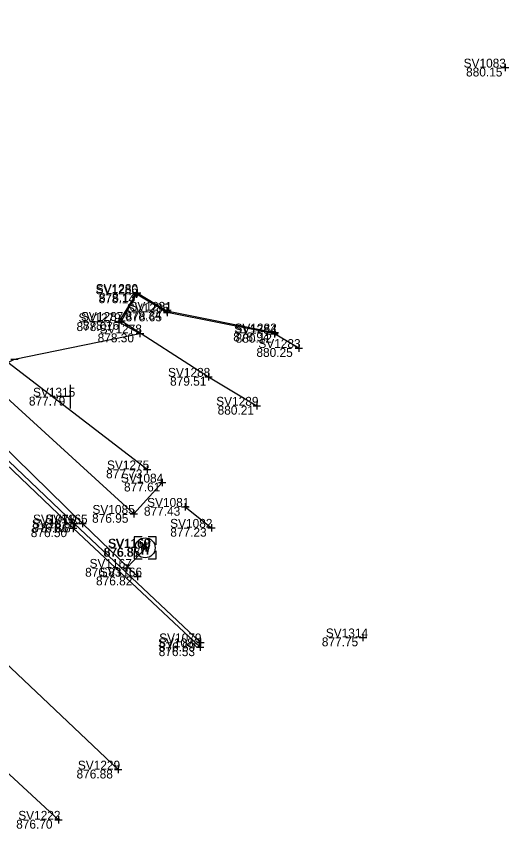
# Model space of a CAD drawing. Extents: x 1480001 to 1480402, y 379235 to 379603.
# Drawn here: x 1480335.4 to 1480401.9, y 379251.1 to 379360.8 of the extents above; entities that cross this region are included whole.
import ezdxf

# ---------------------------------------------------------------- set-up
doc = ezdxf.new("R2010")
doc.units = 0
for name, color, linetype in [('BD_X_Building', 7, 'Continuous'), ('PM_P_CL_Double_Solid', 7, 'Continuous'), ('PM_X_Lane_Line', 7, 'Continuous'), ('PV_X_Curb', 7, 'Continuous'), ('PV_X_Driveway', 7, 'Continuous'), ('PV_X_Walk', 7, 'Continuous'), ('SN_X_Public', 7, 'Continuous'), ('SV_X_Shot_Marker', 7, 'Continuous'), ('SV_X_Text_Elevation', 7, 'Continuous'), ('SV_X_Text_Name', 7, 'Continuous'), ('UT_X_Water', 7, 'Continuous'), ('UT_X_Water_Cells', 7, 'Continuous')]:
    doc.layers.add(name, color=color, linetype=linetype)

msp = doc.modelspace()

# ---------------------------------------------------------------- linework, layer by layer
at = {"layer": 'BD_X_Building'}
msp.add_line((1480358.23, 379294.55), (1480361.77, 379291.72), dxfattribs=at)
at = {"layer": 'PM_P_CL_Double_Solid'}
msp.add_lwpolyline([(1480349.17, 379259.05), (1480326.95, 379280.06), (1480305.57, 379299.92), (1480284.39, 379319.58), (1480263.3, 379339.27), (1480242.58, 379359.21), (1480224.61, 379376.17), (1480208.19, 379391.53)], dxfattribs=at)
at = {"layer": 'PM_X_Lane_Line'}
msp.add_line((1480333.91, 379258.95), (1480341.1, 379252.27), dxfattribs=at)
at = {"layer": 'PV_X_Curb'}
for points in [[(1480221.5, 379406.23), (1480232.96, 379395.54), (1480249.63, 379380.04), (1480261.65, 379368.64), (1480263.97, 379366.42), (1480266.34, 379364.24), (1480284.17, 379347.24), (1480298.68, 379333.41), (1480300.4, 379332.23), (1480315.33, 379318.04), (1480323.87, 379309.98), (1480343.09, 379291.66), (1480360.25, 379275.58)], [(1480221.91, 379406.57), (1480233.16, 379396.15), (1480249.93, 379380.31), (1480262.01, 379368.89), (1480262.35, 379369.25), (1480264.51, 379367.17), (1480266.63, 379365.06), (1480266.41, 379364.74), (1480284.49, 379347.54), (1480298.92, 379333.84), (1480300.74, 379332.59), (1480315.86, 379318.31), (1480323.78, 379310.75), (1480324.55, 379310.08), (1480343.24, 379292.3), (1480360.29, 379276.24)]]:
    msp.add_lwpolyline(points, dxfattribs=at)
at = {"layer": 'PV_X_Driveway'}
msp.add_lwpolyline([(1480353.09, 379299.61), (1480334.27, 379314.05), (1480335.15, 379314.52), (1480352.11, 379317.98), (1480349.25, 379319.5), (1480351.71, 379323.45), (1480355.72, 379321.04), (1480370.32, 379318.11)], dxfattribs=at)
at = {"layer": 'PV_X_Walk'}
for points in [[(1480355.12, 379297.83), (1480351.29, 379293.6), (1480334.1, 379309.33), (1480328.21, 379315.43), (1480328.74, 379316.33), (1480319.91, 379324.49), (1480307.61, 379335.13), (1480302.9, 379338.36), (1480281.82, 379358.41), (1480285.61, 379363.39), (1480280.44, 379367.11), (1480277.22, 379362.83), (1480260.82, 379378.02), (1480244.57, 379393.15), (1480235.61, 379401.34), (1480215.34, 379421.05)], [(1480373.55, 379316.01), (1480370.27, 379317.93), (1480355.8, 379320.82), (1480351.65, 379323.27), (1480349.6, 379319.67), (1480361.36, 379312.12), (1480367.87, 379308.21)]]:
    msp.add_lwpolyline(points, dxfattribs=at)
at = {"layer": 'SN_X_Public'}
for p, q in [((1480342.69, 379311.04), (1480342.69, 379307.84)), ((1480342.69, 379309.44), (1480341.09, 379309.44))]:
    msp.add_line(p, q, dxfattribs=at)
at = {"layer": 'SV_X_Shot_Marker'}
for p, q in [((1480401.4, 379354.4), (1480401.4, 379353.4)), ((1480400.9, 379353.9), (1480401.9, 379353.9)), ((1480401.4, 379353.9), (1480401.4, 379353.9)), ((1480351.15, 379323.27), (1480352.15, 379323.27)), ((1480351.21, 379323.45), (1480352.21, 379323.45)), ((1480351.65, 379323.77), (1480351.65, 379322.77)), ((1480351.65, 379323.27), (1480351.65, 379323.27)), ((1480351.71, 379323.95), (1480351.71, 379322.95)), ((1480351.71, 379323.45), (1480351.71, 379323.45)), ((1480355.22, 379321.04), (1480356.22, 379321.04)), ((1480355.72, 379321.54), (1480355.72, 379320.54)), ((1480355.72, 379321.04), (1480355.72, 379321.04)), ((1480355.8, 379321.32), (1480355.8, 379320.32)), ((1480349.25, 379320), (1480349.25, 379319)), ((1480349.6, 379320.17), (1480349.6, 379319.17)), ((1480355.3, 379320.82), (1480356.3, 379320.82)), ((1480355.8, 379320.82), (1480355.8, 379320.82)), ((1480348.75, 379319.5), (1480349.75, 379319.5)), ((1480349.1, 379319.67), (1480350.1, 379319.67)), ((1480349.25, 379319.5), (1480349.25, 379319.5)), ((1480349.6, 379319.67), (1480349.6, 379319.67)), ((1480351.61, 379317.98), (1480352.61, 379317.98)), ((1480352.11, 379318.48), (1480352.11, 379317.48)), ((1480352.11, 379317.98), (1480352.11, 379317.98)), ((1480369.77, 379317.93), (1480370.77, 379317.93)), ((1480369.82, 379318.11), (1480370.82, 379318.11)), ((1480370.27, 379318.43), (1480370.27, 379317.43)), ((1480370.27, 379317.93), (1480370.27, 379317.93)), ((1480370.32, 379318.61), (1480370.32, 379317.61)), ((1480370.32, 379318.11), (1480370.32, 379318.11)), ((1480373.05, 379316.01), (1480374.05, 379316.01)), ((1480373.55, 379316.51), (1480373.55, 379315.51)), ((1480373.55, 379316.01), (1480373.55, 379316.01)), ((1480334.65, 379314.52), (1480335.65, 379314.52)), ((1480361.36, 379312.62), (1480361.36, 379311.62)), ((1480360.86, 379312.12), (1480361.86, 379312.12)), ((1480361.36, 379312.12), (1480361.36, 379312.12)), ((1480367.37, 379308.21), (1480368.37, 379308.21)), ((1480367.87, 379308.71), (1480367.87, 379307.71)), ((1480367.87, 379308.21), (1480367.87, 379308.21)), ((1480352.59, 379299.61), (1480353.59, 379299.61)), ((1480353.09, 379300.11), (1480353.09, 379299.11)), ((1480353.09, 379299.61), (1480353.09, 379299.61)), ((1480355.12, 379298.33), (1480355.12, 379297.33)), ((1480354.62, 379297.83), (1480355.62, 379297.83)), ((1480355.12, 379297.83), (1480355.12, 379297.83)), ((1480358.23, 379295.05), (1480358.23, 379294.05)), ((1480350.79, 379293.6), (1480351.79, 379293.6)), ((1480351.29, 379294.1), (1480351.29, 379293.1)), ((1480351.29, 379293.6), (1480351.29, 379293.6)), ((1480357.73, 379294.55), (1480358.73, 379294.55)), ((1480358.23, 379294.55), (1480358.23, 379294.55)), ((1480343.24, 379292.8), (1480343.24, 379291.8)), ((1480344.34, 379292.81), (1480344.34, 379291.81)), ((1480342.59, 379291.66), (1480343.59, 379291.66)), ((1480342.74, 379292.3), (1480343.74, 379292.3)), ((1480343.09, 379292.16), (1480343.09, 379291.16)), ((1480343.09, 379291.66), (1480343.09, 379291.66)), ((1480343.24, 379292.3), (1480343.24, 379292.3)), ((1480343.84, 379292.31), (1480344.84, 379292.31)), ((1480344.34, 379292.31), (1480344.34, 379292.31)), ((1480361.27, 379291.72), (1480362.27, 379291.72)), ((1480361.77, 379292.22), (1480361.77, 379291.22)), ((1480361.77, 379291.72), (1480361.77, 379291.72)), ((1480352.89, 379289.53), (1480352.89, 379288.53)), ((1480352.39, 379289.03), (1480353.39, 379289.03)), ((1480352.89, 379289.03), (1480352.89, 379289.03)), ((1480349.82, 379286.31), (1480350.82, 379286.31)), ((1480350.32, 379286.81), (1480350.32, 379285.81)), ((1480350.32, 379286.31), (1480350.32, 379286.31)), ((1480351.28, 379285.14), (1480352.28, 379285.14)), ((1480351.78, 379285.64), (1480351.78, 379284.64)), ((1480351.78, 379285.14), (1480351.78, 379285.14)), ((1480382.22, 379277.41), (1480382.22, 379276.41)), ((1480359.79, 379276.24), (1480360.79, 379276.24)), ((1480360.25, 379276.08), (1480360.25, 379275.08)), ((1480360.29, 379276.74), (1480360.29, 379275.74)), ((1480360.29, 379276.24), (1480360.29, 379276.24)), ((1480381.72, 379276.91), (1480382.72, 379276.91)), ((1480382.22, 379276.91), (1480382.22, 379276.91)), ((1480359.75, 379275.58), (1480360.75, 379275.58)), ((1480360.25, 379275.58), (1480360.25, 379275.58)), ((1480348.67, 379259.05), (1480349.67, 379259.05)), ((1480349.17, 379259.55), (1480349.17, 379258.55)), ((1480349.17, 379259.05), (1480349.17, 379259.05)), ((1480340.6, 379252.27), (1480341.6, 379252.27)), ((1480341.1, 379252.77), (1480341.1, 379251.77)), ((1480341.1, 379252.27), (1480341.1, 379252.27))]:
    msp.add_line(p, q, dxfattribs=at)
at = {"layer": 'UT_X_Water'}
msp.add_line((1480350.32, 379286.31), (1480352.89, 379289.03), dxfattribs=at)
msp.add_lwpolyline([(1480212.63, 379415.68), (1480231.59, 379398.24), (1480249.49, 379381.83), (1480253.44, 379378.96), (1480259.28, 379374.54), (1480264.17, 379372.87), (1480269.43, 379369.25), (1480270.6, 379368.16), (1480270.76, 379365.9), (1480271.19, 379363.73), (1480285.47, 379347.96), (1480298.85, 379335.61), (1480313.01, 379322.71), (1480330.75, 379305.6), (1480344.34, 379292.31), (1480351.78, 379285.14)], dxfattribs=at)
at = {"layer": 'UT_X_Water_Cells'}
msp.add_line((1480352.81, 379289.01), (1480352.81, 379289.01), dxfattribs=at)
for points in [[(1480352.41, 379290.51), (1480351.31, 379290.51), (1480351.31, 379289.41)], [(1480354.31, 379289.41), (1480354.31, 379290.51), (1480353.21, 379290.51)], [(1480352.14, 379289.91), (1480352.47, 379288.11), (1480352.81, 379289.91), (1480353.14, 379288.11), (1480353.47, 379289.91)], [(1480351.31, 379288.61), (1480351.31, 379287.51), (1480352.41, 379287.51)], [(1480353.21, 379287.51), (1480354.31, 379287.51), (1480354.31, 379288.61)]]:
    msp.add_lwpolyline(points, dxfattribs=at)
msp.add_circle((1480352.81, 379289.01), 1.35, dxfattribs=at)

# ---------------------------------------------------------------- texts
at = {"layer": 'SV_X_Text_Elevation'}
for s, p in [('880.15', (1480396.14, 379352.7)), ('878.14', (1480346.52, 379322.07)), ('878.13', (1480346.58, 379322.25)), ('878.34', (1480350.1, 379319.84)), ('878.65', (1480350.17, 379319.62)), ('878.07', (1480343.54, 379318.3)), ('878.16', (1480344.39, 379318.47)), ('878.30', (1480346.39, 379316.78)), ('878.94', (1480364.7, 379316.91)), ('880.12', (1480365.02, 379316.73)), ('880.25', (1480367.83, 379314.81)), ('879.51', (1480356.17, 379310.92)), ('877.79', (1480337.11, 379308.24)), ('880.21', (1480362.59, 379307.01)), ('877.73', (1480347.53, 379298.41)), ('877.61', (1480349.95, 379296.63)), ('876.95', (1480345.64, 379292.4)), ('877.43', (1480352.64, 379293.35)), ('876.50', (1480337.36, 379290.46)), ('876.86', (1480337.54, 379291.1)), ('876.87', (1480338.72, 379291.11)), ('877.23', (1480356.2, 379290.52)), ('876.85', (1480347.18, 379287.81)), ('876.87', (1480347.26, 379287.83)), ('876.83', (1480344.7, 379285.11)), ('876.82', (1480346.17, 379283.94)), ('876.89', (1480354.66, 379275.04)), ('877.75', (1480376.66, 379275.71)), ('876.53', (1480354.63, 379274.38)), ('876.88', (1480343.54, 379257.85)), ('876.70', (1480335.39, 379251.07))]:
    msp.add_text(s, height=1.2, dxfattribs=at).set_placement(p)
at = {"layer": 'SV_X_Text_Name'}
for s, p in [('SV1083', (1480395.81, 379353.9)), ('SV1286', (1480346.11, 379323.27)), ('SV1280', (1480346.14, 379323.45)), ('SV1281', (1480350.69, 379321.04)), ('SV1285', (1480350.34, 379320.82)), ('SV1279', (1480343.8, 379319.5)), ('SV1287', (1480344.14, 379319.67)), ('SV1278', (1480346.66, 379317.98)), ('SV1284', (1480364.82, 379317.93)), ('SV1282', (1480364.87, 379318.11)), ('SV1283', (1480368.09, 379316.01)), ('SV1288', (1480355.89, 379312.12)), ('SV1315', (1480337.66, 379309.44)), ('SV1289', (1480362.4, 379308.21)), ('SV1275', (1480347.65, 379299.61)), ('SV1084', (1480349.54, 379297.83)), ('SV1085', (1480345.69, 379293.6)), ('SV1081', (1480353.07, 379294.55)), ('SV1077', (1480337.51, 379291.66)), ('SV1078', (1480337.66, 379292.3)), ('SV1165', (1480339.32, 379292.31)), ('SV1082', (1480356.18, 379291.72)), ('SV1169', (1480347.77, 379289.01)), ('SV1168', (1480347.85, 379289.03)), ('SV1167', (1480345.3, 379286.31)), ('SV1166', (1480346.68, 379285.14)), ('SV1079', (1480354.7, 379276.24)), ('SV1314', (1480377.2, 379276.91)), ('SV1080', (1480354.55, 379275.58)), ('SV1229', (1480343.72, 379259.05)), ('SV1222', (1480335.67, 379252.27))]:
    msp.add_text(s, height=1.2, dxfattribs=at).set_placement(p)

doc.saveas('drawing.dxf')
